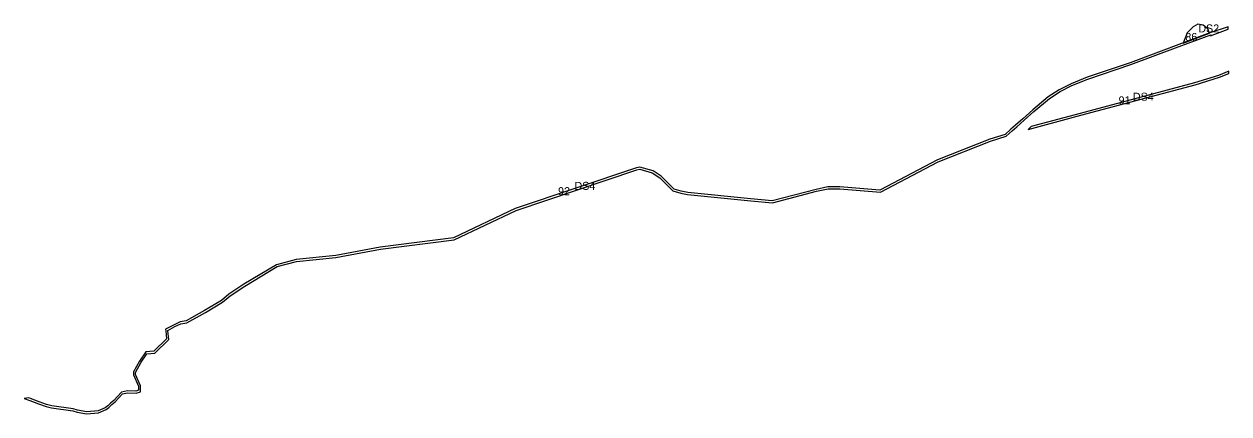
# Model space of a CAD drawing. Extents: x -477001 to -465642, y -1158278 to -1150672.
# Drawn here: x -467449 to -465642, y -1153072 to -1152488 of the extents above; entities that cross this region are included whole.
import ezdxf

# ---------------------------------------------------------------- set-up
doc = ezdxf.new("R2010")
doc.units = 0
for name, color, linetype in [('VPS_id', 7, 'Continuous'), ('VPS_n', 7, 'Continuous'), ('vyvlastneni_n', 7, 'Continuous')]:
    doc.layers.add(name, color=color, linetype=linetype)

msp = doc.modelspace()

# ---------------------------------------------------------------- linework, layer by layer
at = {"layer": 'VPS_n'}
for p, q in [((-465643, -1152494.7), (-465643.1, -1152491.6)), ((-465710.6, -1152516.1), (-465671.1, -1152501.3)), ((-465669.3, -1152505.1), (-465662.8, -1152502.6)), ((-465669.2, -1152503.8), (-465669.3, -1152505.1)), ((-465642.2, -1152561.6), (-465641.9, -1152558.2)), ((-465938.3, -1152641.5), (-465943.1, -1152645.9)), ((-467205.9, -1152933), (-467214.8, -1152934.5)), ((-467213.9, -1152937.4), (-467204.9, -1152935.9)), ((-467441.8, -1153048.4), (-467448.7, -1153049.2))]:
    msp.add_line(p, q, dxfattribs=at)
for points in [[(-465643.1, -1152491.6), (-465670.3, -1152501), (-465789.9, -1152545.7), (-465854.4, -1152567.3), (-465878.5, -1152577.1), (-465896.4, -1152586.2), (-465912.9, -1152596.9), (-465936.1, -1152616.3), (-465951.1, -1152629.7), (-465962.1, -1152639.5), (-465968.7, -1152645.5), (-465977.5, -1152653.2)], [(-465671.1, -1152501.3), (-465673.6, -1152494.6), (-465680.5, -1152489.2), (-465688.7, -1152487.7), (-465695.6, -1152491.8), (-465704.3, -1152500.6), (-465710.6, -1152516.1)], [(-465662.8, -1152502.6), (-465643, -1152495.3), (-465643, -1152494.7)], [(-465976, -1152655.9), (-465966.7, -1152647.7), (-465960.1, -1152641.7), (-465949.1, -1152631.9), (-465934.2, -1152618.6), (-465911.1, -1152599.3), (-465894.9, -1152588.9), (-465877.2, -1152579.9), (-465853.4, -1152570.1), (-465788.9, -1152548.5), (-465721.8, -1152523.4), (-465669.2, -1152503.8)], [(-465943.1, -1152645.9), (-465863.9, -1152624.4), (-465692.7, -1152578.6), (-465656.2, -1152567.5), (-465642.2, -1152561.6)], [(-465641.9, -1152558.2), (-465657.3, -1152564.7), (-465693.5, -1152575.7), (-465864.7, -1152621.6), (-465938.3, -1152641.5)], [(-465977.5, -1152653.2), (-466000.4, -1152660.4), (-466079.1, -1152691.4), (-466165.2, -1152736.6), (-466225.2, -1152732), (-466243.2, -1152731.6), (-466261, -1152735.6), (-466326.7, -1152752.9), (-466358.7, -1152750), (-466453.2, -1152740.5), (-466463.2, -1152738.4), (-466474, -1152735.2), (-466493.5, -1152715.7), (-466505.4, -1152707.9), (-466525.3, -1152702.4), (-466530.3, -1152703.2), (-466712.1, -1152764.4), (-466804.8, -1152808.2), (-466914.5, -1152822.2), (-466981.4, -1152834.6), (-467040.8, -1152840.9), (-467070.4, -1152848.7), (-467119.3, -1152878), (-467141.7, -1152892.8), (-467152.7, -1152902.5), (-467178.1, -1152917.5), (-467205.9, -1152933)], [(-467204.9, -1152935.9), (-467176.6, -1152920.1), (-467151, -1152905), (-467139.8, -1152895.2), (-467117.7, -1152880.6), (-467069.2, -1152851.5), (-467040.2, -1152843.9), (-466981, -1152837.6), (-466914, -1152825.2), (-466803.9, -1152811.1), (-466710.9, -1152767.2), (-466529.6, -1152706.1), (-466525.4, -1152705.5), (-466506.6, -1152710.6), (-466495.4, -1152718.1), (-466475.6, -1152737.8), (-466463.9, -1152741.4), (-466453.6, -1152743.5), (-466358.9, -1152753), (-466326.5, -1152756), (-466260.3, -1152738.5), (-466242.9, -1152734.6), (-466225.4, -1152735), (-466164.6, -1152739.6), (-466077.9, -1152694.1), (-465999.4, -1152663.2), (-465976, -1152655.9)], [(-467448.7, -1153049.2), (-467440.3, -1153052.1), (-467427, -1153057.1), (-467415.7, -1153061.3), (-467407.7, -1153063.1), (-467375.9, -1153067.8), (-467369.4, -1153069.6), (-467355, -1153072.4), (-467337.1, -1153070.7), (-467325.9, -1153065.8), (-467321.5, -1153062.7), (-467317.3, -1153058.3), (-467312.2, -1153054.4), (-467301, -1153042.4), (-467293.6, -1153041), (-467280.8, -1153041.1), (-467274, -1153039.3), (-467274.1, -1153030.3), (-467281.6, -1153013.3), (-467281.7, -1153010.2), (-467273.3, -1152994.6), (-467264.7, -1152982.1), (-467252.7, -1152981.4), (-467231.8, -1152960.9), (-467233.2, -1152947.7), (-467233.3, -1152947.1), (-467222.6, -1152941.3), (-467213.9, -1152937.4)], [(-467214.8, -1152934.5), (-467223.9, -1152938.6), (-467236.5, -1152945.4), (-467236.2, -1152948), (-467235, -1152959.8), (-467254, -1152978.4), (-467266.3, -1152979.2), (-467275.8, -1152993.1), (-467284.7, -1153009.4), (-467284.5, -1153013.9), (-467277.1, -1153030.9), (-467277, -1153037), (-467281.2, -1153038.1), (-467293.8, -1153038), (-467302.5, -1153039.6), (-467314.2, -1153052.1), (-467319.3, -1153056.1), (-467323.4, -1153060.4), (-467327.4, -1153063.1), (-467337.9, -1153067.8), (-467354.8, -1153069.4), (-467368.7, -1153066.6), (-467375.3, -1153064.8), (-467407.2, -1153060.1), (-467414.9, -1153058.4), (-467426, -1153054.3), (-467439.3, -1153049.3), (-467441.8, -1153048.4)]]:
    msp.add_lwpolyline(points, dxfattribs=at)
at = {"layer": 'vyvlastneni_n'}
for p, q in [((-465643, -1152494.7), (-465643.1, -1152491.6)), ((-465710.6, -1152516.1), (-465671.1, -1152501.3)), ((-465669.3, -1152505.1), (-465662.8, -1152502.6)), ((-465669.2, -1152503.8), (-465669.3, -1152505.1)), ((-465642.2, -1152561.6), (-465641.9, -1152558.2)), ((-465938.3, -1152641.5), (-465943.1, -1152645.9)), ((-467205.9, -1152933), (-467214.8, -1152934.5)), ((-467213.9, -1152937.4), (-467204.9, -1152935.9)), ((-467441.8, -1153048.4), (-467448.7, -1153049.2))]:
    msp.add_line(p, q, dxfattribs=at)
for points in [[(-465643.1, -1152491.6), (-465670.3, -1152501), (-465789.9, -1152545.7), (-465854.4, -1152567.3), (-465878.5, -1152577.1), (-465896.4, -1152586.2), (-465912.9, -1152596.9), (-465936.1, -1152616.3), (-465951.1, -1152629.7), (-465962.1, -1152639.5), (-465968.7, -1152645.5), (-465977.5, -1152653.2)], [(-465671.1, -1152501.3), (-465673.6, -1152494.6), (-465680.5, -1152489.2), (-465688.7, -1152487.7), (-465695.6, -1152491.8), (-465704.3, -1152500.6), (-465710.6, -1152516.1)], [(-465662.8, -1152502.6), (-465643, -1152495.3), (-465643, -1152494.7)], [(-465976, -1152655.9), (-465966.7, -1152647.7), (-465960.1, -1152641.7), (-465949.1, -1152631.9), (-465934.2, -1152618.6), (-465911.1, -1152599.3), (-465894.9, -1152588.9), (-465877.2, -1152579.9), (-465853.4, -1152570.1), (-465788.9, -1152548.5), (-465721.8, -1152523.4), (-465669.2, -1152503.8)], [(-465943.1, -1152645.9), (-465863.9, -1152624.4), (-465692.7, -1152578.6), (-465656.2, -1152567.5), (-465642.2, -1152561.6)], [(-465641.9, -1152558.2), (-465657.3, -1152564.7), (-465693.5, -1152575.7), (-465864.7, -1152621.6), (-465938.3, -1152641.5)], [(-465977.5, -1152653.2), (-466000.4, -1152660.4), (-466079.1, -1152691.4), (-466165.2, -1152736.6), (-466225.2, -1152732), (-466243.2, -1152731.6), (-466261, -1152735.6), (-466326.7, -1152752.9), (-466358.7, -1152750), (-466453.2, -1152740.5), (-466463.2, -1152738.4), (-466474, -1152735.2), (-466493.5, -1152715.7), (-466505.4, -1152707.9), (-466525.3, -1152702.4), (-466530.3, -1152703.2), (-466712.1, -1152764.4), (-466804.8, -1152808.2), (-466914.5, -1152822.2), (-466981.4, -1152834.6), (-467040.8, -1152840.9), (-467070.4, -1152848.7), (-467119.3, -1152878), (-467141.7, -1152892.8), (-467152.7, -1152902.5), (-467178.1, -1152917.5), (-467205.9, -1152933)], [(-467204.9, -1152935.9), (-467176.6, -1152920.1), (-467151, -1152905), (-467139.8, -1152895.2), (-467117.7, -1152880.6), (-467069.2, -1152851.5), (-467040.2, -1152843.9), (-466981, -1152837.6), (-466914, -1152825.2), (-466803.9, -1152811.1), (-466710.9, -1152767.2), (-466529.6, -1152706.1), (-466525.4, -1152705.5), (-466506.6, -1152710.6), (-466495.4, -1152718.1), (-466475.6, -1152737.8), (-466463.9, -1152741.4), (-466453.6, -1152743.5), (-466358.9, -1152753), (-466326.5, -1152756), (-466260.3, -1152738.5), (-466242.9, -1152734.6), (-466225.4, -1152735), (-466164.6, -1152739.6), (-466077.9, -1152694.1), (-465999.4, -1152663.2), (-465976, -1152655.9)], [(-467448.7, -1153049.2), (-467440.3, -1153052.1), (-467427, -1153057.1), (-467415.7, -1153061.3), (-467407.7, -1153063.1), (-467375.9, -1153067.8), (-467369.4, -1153069.6), (-467355, -1153072.4), (-467337.1, -1153070.7), (-467325.9, -1153065.8), (-467321.5, -1153062.7), (-467317.3, -1153058.3), (-467312.2, -1153054.4), (-467301, -1153042.4), (-467293.6, -1153041), (-467280.8, -1153041.1), (-467274, -1153039.3), (-467274.1, -1153030.3), (-467281.6, -1153013.3), (-467281.7, -1153010.2), (-467273.3, -1152994.6), (-467264.7, -1152982.1), (-467252.7, -1152981.4), (-467231.8, -1152960.9), (-467233.2, -1152947.7), (-467233.3, -1152947.1), (-467222.6, -1152941.3), (-467213.9, -1152937.4)], [(-467214.8, -1152934.5), (-467223.9, -1152938.6), (-467236.5, -1152945.4), (-467236.2, -1152948), (-467235, -1152959.8), (-467254, -1152978.4), (-467266.3, -1152979.2), (-467275.8, -1152993.1), (-467284.7, -1153009.4), (-467284.5, -1153013.9), (-467277.1, -1153030.9), (-467277, -1153037), (-467281.2, -1153038.1), (-467293.8, -1153038), (-467302.5, -1153039.6), (-467314.2, -1153052.1), (-467319.3, -1153056.1), (-467323.4, -1153060.4), (-467327.4, -1153063.1), (-467337.9, -1153067.8), (-467354.8, -1153069.4), (-467368.7, -1153066.6), (-467375.3, -1153064.8), (-467407.2, -1153060.1), (-467414.9, -1153058.4), (-467426, -1153054.3), (-467439.3, -1153049.3), (-467441.8, -1153048.4)]]:
    msp.add_lwpolyline(points, dxfattribs=at)

# ---------------------------------------------------------------- texts
at = {"layer": 'VPS_id'}
for s, p in [('86', (-465707.2, -1152513)), ('91', (-465807.3, -1152608.1)), ('92', (-466647.9, -1152744.3))]:
    msp.add_text(s, height=12, dxfattribs=at).set_placement(p)
at = {"layer": 'VPS_n'}
for s, p in [('DS2', (-465687.7, -1152500.2)), ('DS4', (-465785.8, -1152602.6)), ('DS4', (-466623.3, -1152736.3))]:
    msp.add_text(s, height=12, dxfattribs=at).set_placement(p)

doc.saveas('drawing.dxf')
